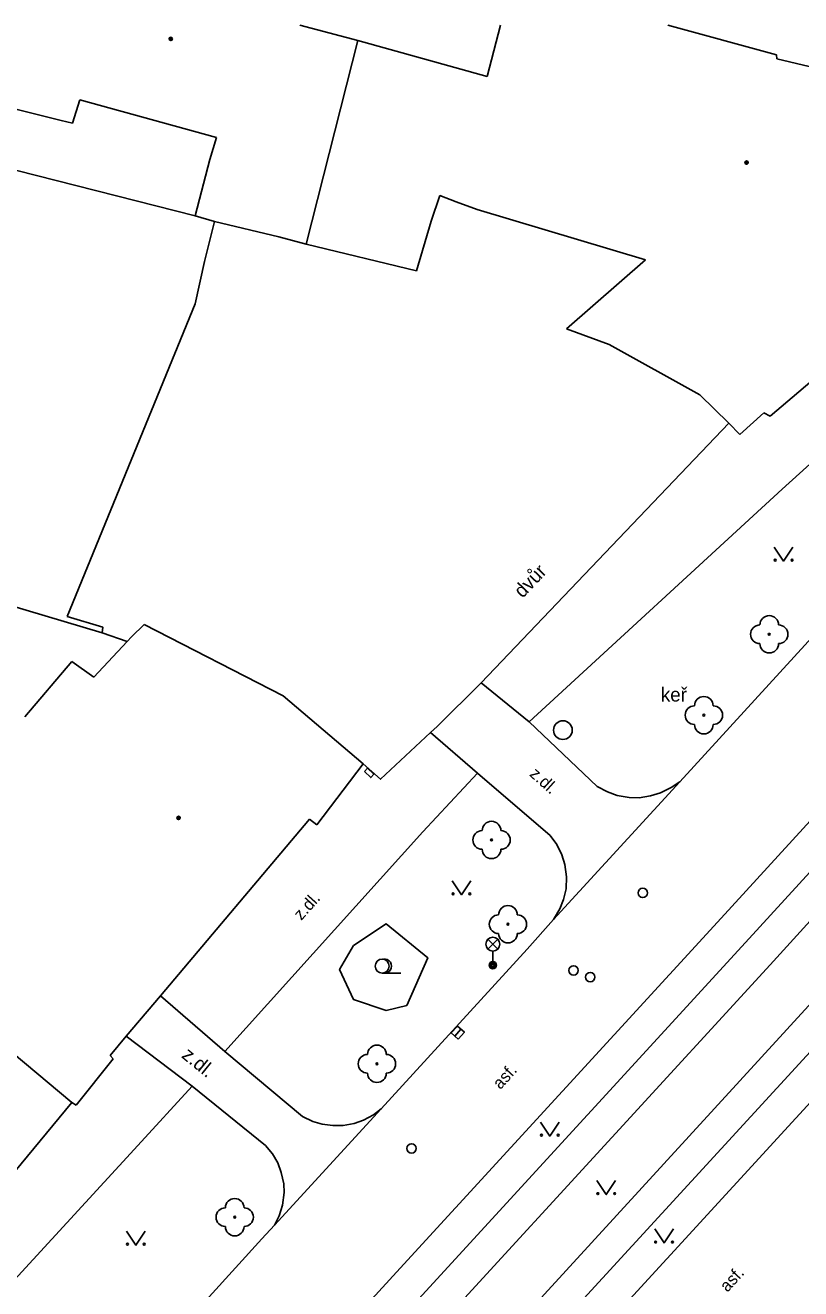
# Model space of a CAD drawing. Extents: x -598932 to -598196, y -1162207 to -1161504.
# Drawn here: x -598441.5 to -598400, y -1161572.8 to -1161505.2 of the extents above; entities that cross this region are included whole.
import ezdxf

# ---------------------------------------------------------------- set-up
doc = ezdxf.new("R2010")
doc.units = 0
for name, color, linetype in [('DOP - rozhrani ploch obecne', 7, 'Continuous'), ('Level 22', 7, 'Continuous'), ('Level 27', 7, 'Continuous'), ('Level 28', 7, 'Continuous'), ('Level 33', 7, 'Continuous'), ('Level 36', 7, 'Continuous'), ('Level 39', 7, 'Continuous'), ('silnoproud - povrch.  znaky a  RIS  skut. velikost', 7, 'Continuous'), ('specificka linie pasportu komunikaci', 7, 'Continuous'), ('TM - budovy zdene_ betonove - VP', 7, 'Continuous'), ('TM - chodniky - VP', 7, 'Continuous'), ('TM - hranice souvisleho porostu (skupiny stromu_ kere)', 7, 'Continuous'), ('TM - komunikace - VP', 7, 'Continuous'), ('TM - MHD - osa koleji', 7, 'Continuous'), ('TM - plot zdeny_ ohradni zed - VP', 7, 'Continuous'), ('TM - popis povrchu', 7, 'Continuous'), ('TM - popis zelene', 7, 'Continuous'), ('TM - poznamka', 7, 'Continuous'), ('TM - rozhrani ploch obecne - VP', 7, 'Continuous'), ('TM - vjezd na pozemek', 7, 'Continuous')]:
    doc.layers.add(name, color=color, linetype=linetype)

msp = doc.modelspace()

# ---------------------------------------------------------------- linework, layer by layer
at = {"layer": 'DOP - rozhrani ploch obecne'}
for points in [[(-598431.41, -1161515.69), (-598431.94, -1161517.83)], [(-598431.94, -1161517.83), (-598432.44, -1161520.09)], [(-598439.28, -1161536.83), (-598432.44, -1161520.09)], [(-598437.38, -1161537.4), (-598439.28, -1161536.83)], [(-598437.42, -1161537.71), (-598437.38, -1161537.4)]]:
    msp.add_lwpolyline(points, dxfattribs=at)
at = {"layer": 'Level 22'}
for centre in [(-598401.72, -1161537.78), (-598405.22, -1161542.11), (-598416.58, -1161548.79), (-598415.7, -1161553.3), (-598422.71, -1161560.77), (-598430.32, -1161568.98)]:
    msp.add_circle(centre, 0.05, dxfattribs=at)
for centre, start, end in [((-598402.22, -1161537.78), 90, 270), ((-598401.72, -1161537.28), 0, 180), ((-598401.22, -1161537.78), 270, 90), ((-598401.72, -1161538.28), 180, 0), ((-598405.22, -1161541.61), 0, 180), ((-598405.72, -1161542.11), 90, 270), ((-598404.72, -1161542.11), 270, 90), ((-598405.22, -1161542.61), 180, 0), ((-598416.58, -1161548.29), 0, 180), ((-598417.08, -1161548.79), 90, 270), ((-598416.08, -1161548.79), 270, 90), ((-598416.58, -1161549.29), 180, 0), ((-598416.2, -1161553.3), 90, 270), ((-598415.7, -1161552.8), 0, 180), ((-598415.2, -1161553.3), 270, 90), ((-598415.7, -1161553.8), 180, 0), ((-598423.21, -1161560.77), 90, 270), ((-598422.71, -1161560.27), 0, 180), ((-598422.21, -1161560.77), 270, 90), ((-598422.71, -1161561.27), 180, 0), ((-598430.82, -1161568.98), 90, 270), ((-598430.32, -1161568.48), 0, 180), ((-598429.82, -1161568.98), 270, 90), ((-598430.32, -1161569.48), 180, 0)]:
    msp.add_arc(centre, 0.5, start, end, dxfattribs=at)
at = {"layer": 'Level 27'}
msp.add_line((-598418.547, -1161559.286), (-598418.213, -1161558.914), dxfattribs=at)
msp.add_lwpolyline([(-598418.361, -1161559.453), (-598418.027, -1161559.081), (-598418.399, -1161558.747), (-598418.733, -1161559.119)], close=True, dxfattribs=at)
msp.add_circle((-598412.76, -1161542.91), 0.5, dxfattribs=at)
at = {"layer": 'Level 28'}
for centre in [(-598408.49, -1161551.62), (-598412.19, -1161555.77), (-598411.3, -1161556.13), (-598420.86, -1161565.3)]:
    msp.add_circle(centre, 0.25, dxfattribs=at)
at = {"layer": 'Level 33'}
for p, q in [((-598416.775, -1161554.63), (-598416.245, -1161554.1)), ((-598416.775, -1161554.1), (-598416.245, -1161554.63)), ((-598416.51, -1161554.74), (-598416.51, -1161555.49))]:
    msp.add_line(p, q, dxfattribs=at)
for centre, radius in [((-598416.51, -1161554.365), 0.375), ((-598416.51, -1161555.49), 0.2), ((-598416.51, -1161555.49), 0.145), ((-598416.51, -1161555.49), 0.0876)]:
    msp.add_circle(centre, radius, dxfattribs=at)
at = {"layer": 'Level 36'}
msp.add_line((-598422.43, -1161555.915), (-598421.43, -1161555.915), dxfattribs=at)
for points in [[(-598401.45, -1161533.11), (-598400.95, -1161533.86), (-598400.45, -1161533.11)], [(-598418.69, -1161550.97), (-598418.19, -1161551.72), (-598417.69, -1161550.97)], [(-598413.96, -1161563.89), (-598413.46, -1161564.64), (-598412.96, -1161563.89)], [(-598410.94, -1161567.02), (-598410.44, -1161567.77), (-598409.94, -1161567.02)], [(-598436.11, -1161569.73), (-598435.61, -1161570.48), (-598435.11, -1161569.73)], [(-598407.85, -1161569.61), (-598407.35, -1161570.36), (-598406.85, -1161569.61)]]:
    msp.add_lwpolyline(points, dxfattribs=at)
for centre, radius in [((-598401.4, -1161533.81), 0.05), ((-598400.501, -1161533.81), 0.05), ((-598418.64, -1161551.67), 0.05), ((-598417.741, -1161551.67), 0.05), ((-598422.43, -1161555.54), 0.375), ((-598413.91, -1161564.59), 0.05), ((-598413.011, -1161564.59), 0.05), ((-598410.89, -1161567.72), 0.05), ((-598409.991, -1161567.72), 0.05), ((-598436.06, -1161570.43), 0.05), ((-598435.161, -1161570.43), 0.05), ((-598407.8, -1161570.31), 0.05), ((-598406.901, -1161570.31), 0.05)]:
    msp.add_circle(centre, radius, dxfattribs=at)
msp.add_arc((-598422.305, -1161555.54), 0.375, 260.40593, 99.59407, dxfattribs=at)
at = {"layer": 'Level 39'}
for centre, radius in [((-598433.74, -1161505.91), 0.09), ((-598433.74, -1161505.91), 0.0398), ((-598402.93, -1161512.53), 0.09), ((-598402.93, -1161512.53), 0.0398), ((-598433.32, -1161547.61), 0.09), ((-598433.32, -1161547.61), 0.0398)]:
    msp.add_circle(centre, radius, dxfattribs=at)
at = {"layer": 'silnoproud - povrch.  znaky a  RIS  skut. velikost'}
for points in [[(-598423.22, -1161544.94), (-598423.38, -1161545.13)], [(-598422.87, -1161545.26), (-598423.04, -1161545.45), (-598423.38, -1161545.13)], [(-598422.87, -1161545.26), (-598423.22, -1161544.94)]]:
    msp.add_lwpolyline(points, dxfattribs=at)
at = {"layer": 'specificka linie pasportu komunikaci'}
for points in [[(-598414.56, -1161542.46), (-598417.14, -1161540.38)], [(-598419.84, -1161543.04), (-598417.33, -1161545.22)], [(-598434.297, -1161557.135), (-598430.85, -1161560.12)], [(-598436.122, -1161559.3), (-598432.6, -1161561.96)]]:
    msp.add_lwpolyline(points, dxfattribs=at)
at = {"layer": 'TM - budovy zdene_ betonove - VP'}
for points in [[(-598426.828, -1161505.182), (-598423.73, -1161506)], [(-598416.81, -1161507.92), (-598416.106, -1161505.182)], [(-598407.148, -1161505.182), (-598401.33, -1161506.76)], [(-598426.49, -1161516.89), (-598423.73, -1161506)], [(-598423.73, -1161506), (-598416.81, -1161507.92)], [(-598401.33, -1161506.76), (-598401.32, -1161506.97)], [(-598401.32, -1161506.97), (-598399.59, -1161507.39)], [(-598442.18, -1161509.64), (-598439.6, -1161510.28)], [(-598438.99, -1161510.42), (-598438.6, -1161509.17)], [(-598438.6, -1161509.17), (-598431.3, -1161511.19)], [(-598439.6, -1161510.28), (-598438.99, -1161510.42)], [(-598431.3, -1161511.19), (-598431.65, -1161512.37)], [(-598431.65, -1161512.37), (-598432.44, -1161515.39)], [(-598419.81, -1161515.66), (-598419.35, -1161514.29)], [(-598419.35, -1161514.29), (-598418.47, -1161514.63)], [(-598418.47, -1161514.63), (-598417.35, -1161515.05)], [(-598417.35, -1161515.05), (-598408.34, -1161517.74)], [(-598432.44, -1161515.39), (-598431.41, -1161515.69)], [(-598431.41, -1161515.69), (-598427.96, -1161516.51)], [(-598420.6, -1161518.32), (-598419.81, -1161515.66)], [(-598427.96, -1161516.51), (-598426.49, -1161516.89)], [(-598426.49, -1161516.89), (-598420.6, -1161518.32)], [(-598408.34, -1161517.74), (-598412.56, -1161521.43)], [(-598412.56, -1161521.43), (-598410.29, -1161522.27)], [(-598410.29, -1161522.27), (-598405.43, -1161524.96)], [(-598397.66, -1161522.69), (-598401.67, -1161526.11)], [(-598403.89, -1161526.48), (-598405.43, -1161524.96)], [(-598403.3, -1161527.08), (-598403.89, -1161526.48)], [(-598402.01, -1161525.92), (-598403.3, -1161527.08)], [(-598401.67, -1161526.11), (-598402.01, -1161525.92)], [(-598435.17, -1161537.25), (-598435.85, -1161537.91)], [(-598435.17, -1161537.25), (-598427.72, -1161541.08)], [(-598435.85, -1161537.91), (-598436.08, -1161538.17)], [(-598436.08, -1161538.17), (-598437.86, -1161540.07)], [(-598439.04, -1161539.24), (-598441.55, -1161542.2)], [(-598437.86, -1161540.07), (-598439.04, -1161539.24)], [(-598427.72, -1161541.08), (-598423.44, -1161544.72)], [(-598423.44, -1161544.72), (-598425.93, -1161547.98)], [(-598426.32, -1161547.67), (-598434.297, -1161557.135), (-598436.122, -1161559.3), (-598436.99, -1161560.33)], [(-598425.93, -1161547.98), (-598426.32, -1161547.67)], [(-598449.07, -1161554.44), (-598439.03, -1161562.84)], [(-598436.99, -1161560.33), (-598436.83, -1161560.51)], [(-598436.83, -1161560.51), (-598438.81, -1161562.98)], [(-598439.03, -1161562.84), (-598446.26, -1161571.57)], [(-598438.81, -1161562.98), (-598439.03, -1161562.84)]]:
    msp.add_lwpolyline(points, dxfattribs=at)
at = {"layer": 'TM - chodniky - VP'}
for points in [[(-598410.93, -1161545.93), (-598414.56, -1161542.46), (-598401.03, -1161530.02), (-598395.47, -1161524.98), (-598393.53, -1161523.38)], [(-598426.69, -1161563.6), (-598430.85, -1161560.12), (-598420.25, -1161548.36), (-598417.33, -1161545.22), (-598413.44, -1161548.55)], [(-598410.93, -1161545.93), (-598410.37, -1161546.221), (-598409.85, -1161546.41), (-598409.222, -1161546.516), (-598408.68, -1161546.53), (-598408.065, -1161546.432), (-598407.53, -1161546.27), (-598406.966, -1161545.989), (-598406.51, -1161545.67)], [(-598413.44, -1161548.55), (-598413.091, -1161549.038), (-598412.81, -1161549.59), (-598412.658, -1161550.107), (-598412.56, -1161550.77), (-598412.594, -1161551.397), (-598412.72, -1161551.97), (-598412.923, -1161552.483), (-598413.26, -1161553.05)], [(-598440.42, -1161577.39), (-598443.92, -1161574.3), (-598435.5, -1161565.14), (-598432.6, -1161561.96), (-598428.67, -1161565.14)], [(-598426.69, -1161563.6), (-598426.144, -1161563.854), (-598425.64, -1161564.01), (-598425.065, -1161564.081), (-598424.52, -1161564.07), (-598423.936, -1161563.963), (-598423.43, -1161563.79), (-598422.895, -1161563.498), (-598422.48, -1161563.18)], [(-598428.67, -1161565.14), (-598428.3, -1161565.59), (-598428.02, -1161566.08), (-598427.83, -1161566.58), (-598427.7, -1161567.19), (-598427.68, -1161567.66), (-598427.76, -1161568.34), (-598427.947, -1161568.902), (-598428.19, -1161569.4)]]:
    msp.add_lwpolyline(points, dxfattribs=at)
at = {"layer": 'TM - hranice souvisleho porostu (skupiny stromu_ kere)'}
msp.add_lwpolyline([(-598421.11, -1161557.65), (-598422.21, -1161557.91), (-598423.97, -1161557.33), (-598424.71, -1161555.73), (-598423.96, -1161554.44), (-598422.22, -1161553.28), (-598419.99, -1161555.09), (-598421.11, -1161557.65)], dxfattribs=at)
at = {"layer": 'TM - komunikace - VP'}
for points in [[(-598387.78, -1161525.36), (-598391.26, -1161529.16), (-598396.37, -1161534.59), (-598406.51, -1161545.67)], [(-598402.99, -1161554.28), (-598395.15, -1161545.69), (-598387.26, -1161537.15), (-598379.33, -1161528.65)], [(-598404.3, -1161552.98), (-598397.42, -1161545.46), (-598390.5, -1161537.96), (-598383.56, -1161530.49)], [(-598406.51, -1161545.67), (-598413.26, -1161553.05)], [(-598437.53, -1161589.28), (-598421.28, -1161571.5), (-598404.3, -1161552.98)], [(-598413.26, -1161553.05), (-598414.68, -1161554.63), (-598422.48, -1161563.18)], [(-598419.9, -1161572.73), (-598402.99, -1161554.28)], [(-598415.2, -1161577.22), (-598398.14, -1161558.61)], [(-598461.46, -1161630.5), (-598453.7, -1161622.02), (-598452.98, -1161621.24), (-598449.69, -1161617.63), (-598448.94, -1161616.86), (-598446.24, -1161613.89), (-598430.16, -1161596.3), (-598413.91, -1161578.52), (-598396.94, -1161560.02)], [(-598422.48, -1161563.18), (-598428.19, -1161569.4)], [(-598428.19, -1161569.4), (-598428.87, -1161570.14), (-598433.1, -1161574.79), (-598434.97, -1161576.83)], [(-598419.9, -1161572.73), (-598436.22, -1161590.56), (-598452.51, -1161608.31), (-598468.46, -1161625.78), (-598485.54, -1161644.42), (-598502.72, -1161663.19)]]:
    msp.add_lwpolyline(points, dxfattribs=at)
at = {"layer": 'TM - MHD - osa koleji'}
for points in [[(-598401.68, -1161555.47), (-598393.84, -1161546.86), (-598385.93, -1161538.31), (-598377.97, -1161529.81)], [(-598391.58, -1161548.88), (-598399.43, -1161557.46), (-598416.46, -1161576.06), (-598432.69, -1161593.78), (-598448.94, -1161611.53), (-598464.9, -1161628.96), (-598482, -1161647.66), (-598499.17, -1161666.42), (-598516.21, -1161685.03)], [(-598401.68, -1161555.47), (-598418.62, -1161573.96), (-598434.92, -1161591.75), (-598451.19, -1161609.52), (-598467.18, -1161626.97)]]:
    msp.add_lwpolyline(points, dxfattribs=at)
at = {"layer": 'TM - plot zdeny_ ohradni zed - VP'}
for points in [[(-598417.14, -1161540.38), (-598403.89, -1161526.48)], [(-598419.48, -1161542.71), (-598419.84, -1161543.04), (-598422.52, -1161545.54), (-598423.44, -1161544.72)]]:
    msp.add_lwpolyline(points, dxfattribs=at)
at = {"layer": 'TM - rozhrani ploch obecne - VP'}
for points in [[(-598452.58, -1161510.27), (-598432.44, -1161515.39)], [(-598437.42, -1161537.71), (-598448.61, -1161534.37)], [(-598436.08, -1161538.17), (-598437.42, -1161537.71)]]:
    msp.add_lwpolyline(points, dxfattribs=at)
at = {"layer": 'TM - vjezd na pozemek'}
msp.add_lwpolyline([(-598417.14, -1161540.38), (-598419.48, -1161542.71)], dxfattribs=at)

# ---------------------------------------------------------------- texts
at = {"layer": 'TM - popis povrchu'}
for s, height, rotation, p in [('z.dl.', 0.65, 318.16572, (-598414.59, -1161545.32)), ('z.dl.', 0.65, 48, (-598426.76, -1161553.13)), ('z.dl.', 0.75, 321, (-598433.21, -1161560.4)), ('asf.', 0.65, 47.5198, (-598416.11, -1161562.18)), ('asf.', 0.65, 47.5198, (-598403.96, -1161573.03))]:
    msp.add_text(s, height=height, rotation=rotation, dxfattribs=at).set_placement(p)
at = {"layer": 'TM - popis zelene'}
msp.add_text('keř', height=0.75, dxfattribs=at).set_placement((-598407.52, -1161541.38))
at = {"layer": 'TM - poznamka'}
msp.add_text('dvůr', height=0.75, rotation=46.37148, dxfattribs=at).set_placement((-598414.92, -1161535.88))

doc.saveas('drawing.dxf')
